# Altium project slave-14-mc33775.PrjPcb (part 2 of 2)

## Sheet dcdc-converter.SchDoc
size A3; DocumentNumber: 9; SheetNumber: 9; SheetTotal: 11; SheetDescription: DC/DC-Converter
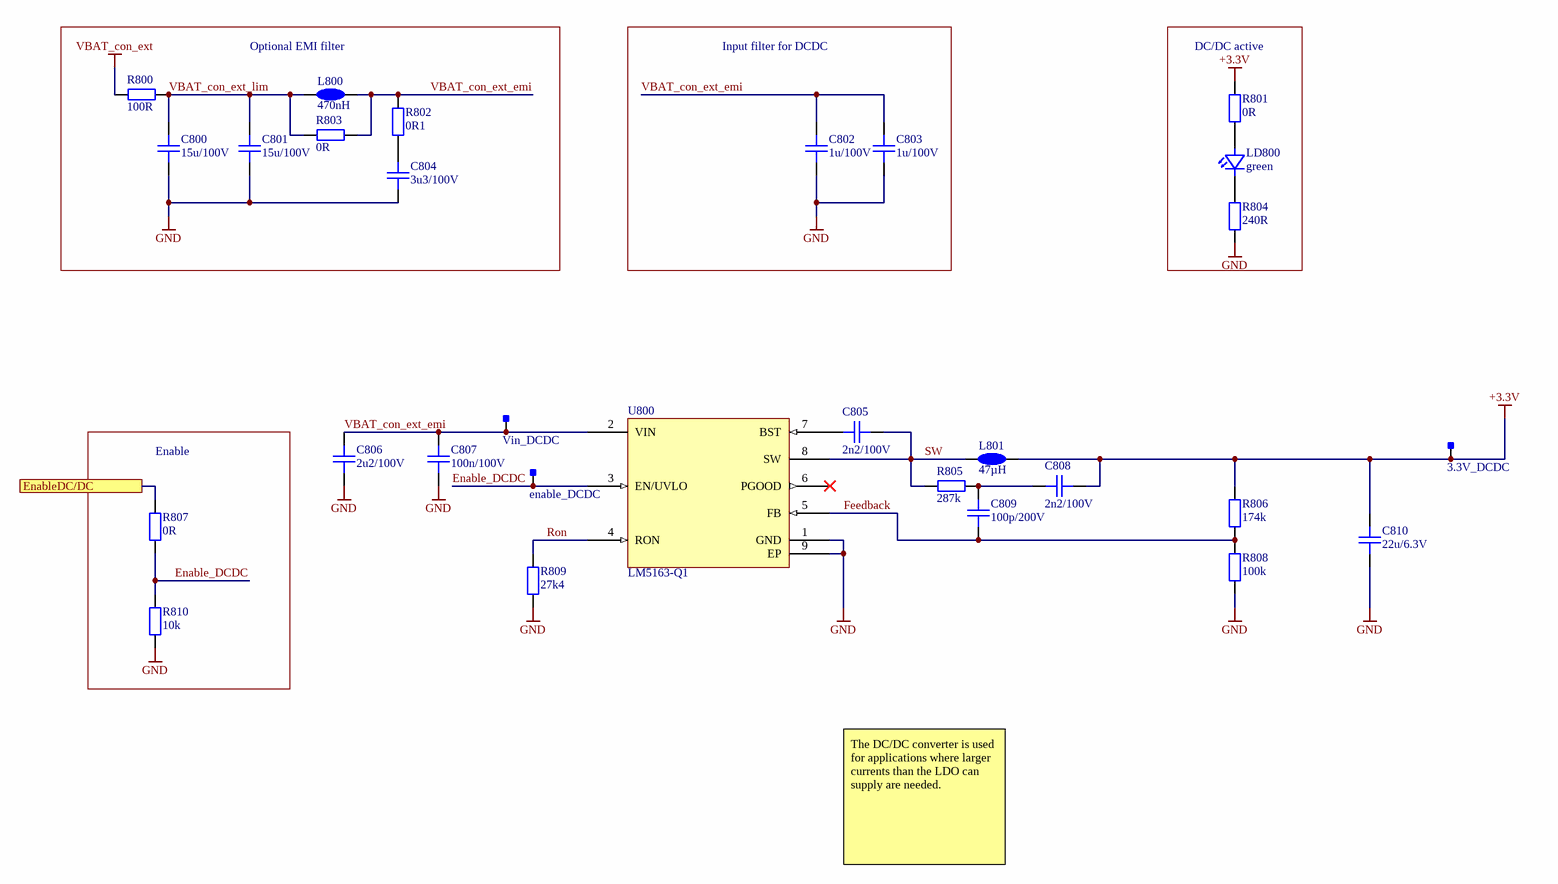
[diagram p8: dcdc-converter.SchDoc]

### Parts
3.3V_DCDC  Testpoint_Square  [Testpoint_S1]  (value not drawn)  (no BOM)
C800  15u/100V  [CAPC6153X67N]
C801  15u/100V  [CAPC6153X67N]
C802  1u/100V  [CAPC3225X25N]
C803  1u/100V  [CAPC3225X25N]
C804  3u3/100V  [CAPC4532X16N]
C805  2n2/100V  [CAPC1005X06N]
C806  2u2/100V  [CAPC3225X25N]
C807  100n/100V  [CAPC1608X08N]
C808  2n2/100V  [CAPC1005X06N]
C809  100p/200V  [CAPC1005X06N]
C810  22u/6.3V  [CAPC3216X18N]
enable_DCDC  Testpoint_Square  [Testpoint_S1]  (value not drawn)  (no BOM)
L800  470nH  [SRP7028A]
L801  47µH  [TYS6045470M-10]
LD800  green  [LEDC1608X07N]
R800  100R  [RESC1608X05N]
R801  0R  [RESC1608X05N]
R802  0R1  [RESC2012X05N]
R803  0R  [RESC1608X05N]
R804  240R  [RESC1608X05N]
R805  287k  [RESC1608X05N]
R806  174k  [RESC1608X05N]
R807  0R  [RESC1608X05N]
R808  100k  [RESC1608X05N]
R809  27k4  [RESC1608X05N]
R810  10k  [RESC1608X05N]
U800  LM5163-Q1  [R-PDSO-G8]
Vin_DCDC  Testpoint_Square  [Testpoint_S1]  (value not drawn)  (no BOM)

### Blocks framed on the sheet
Optional EMI filter: C800 C801 C804 L800 R800 R802 R803
Input filter for DCDC: C802 C803
DC/DC active: LD800 R801 R804
Enable: R807 R810

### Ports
EnableDC/DC

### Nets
+3.3V: 3.3V_DCDC.1 C808.2 C810.2 L801.2 R801.2 R806.2
GND: C800.1 C801.1 C802.1 C803.1 C804.1 C806.1 C807.1 C810.1 R804.1 R808.1 R809.1 R810.2 U800.1(GND) U800.9(EP)
VBAT_con_ext: R800.1
Enable_DCDC: enable_DCDC.1 R807.2 R810.1 U800.3(EN/UVLO)
Feedback: C809.1 R806.1 R808.2 U800.5(FB)
Ron: R809.2 U800.4(RON)
SW: C805.2 L801.1 R805.1 U800.8(SW)
VBAT_con_ext_emi: C802.2 C803.2 C806.2 C807.2 L800.2 R802.2 R803.2 U800.2(VIN) Vin_DCDC.1
VBAT_con_ext_lim: C800.2 C801.2 L800.1 R800.2 R803.1
NetC804_2: C804.2 R802.1
NetC805_1: C805.1 U800.7(BST)
NetC808_1: C808.1 C809.2 R805.2
NetLD800_1: LD800.1(C) R804.2
NetLD800_2: LD800.2(A) R801.1
NetR601_2: R807.1 ; port EnableDC/DC

Not connected (* = marked no-connect by the designer): U800 6(PGOOD)*

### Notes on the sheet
- The DC/DC converter is used for applications where larger currents than the LDO can supply are needed.

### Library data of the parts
3.3V_DCDC enable_DCDC Vin_DCDC = Testpoint_Square: Testpoint, square; Automotive Qualified: False
C800 C801 = gen_C_ceramic_15u_100V_X7R_2220: Stacked MLCC; Capacitance: 15u; Rated Voltage: 100V; Dielectric: X7R; Case EIA: 2220; Case Metric: 5750; Automotive Qualified: True
C802 C803 = gen_C_ceramic_1u_100V_X7R_1210: MLCC; Capacitance: 1u; Rated Voltage: 100V; Dielectric: X7R; Case EIA: 1210; Case Metric: 3225; AVT Set: x; Automotive Qualified: True
C804 = gen_C_ceramic_3u3_100V_X7R_1812: MLCC; Capacitance: 3u3; Rated Voltage: 100V; Dielectric: X7R; Case EIA: 1812; Case Metric: 4532; Automotive Qualified: True
C805 = gen_C_ceramic_2n2_100V_X7R_0402: MLCC; Capacitance: 2n2; Rated Voltage: 100V; Dielectric: X7R; Case EIA: 0402; Case Metric: 1005; Automotive Qualified: True; PnP Package: 0402C
C806 = gen_C_ceramic_2u2_100V_X7R_1210: MLCC; Capacitance: 2u2; Rated Voltage: 100V; Dielectric: X7R; Case EIA: 1210; Case Metric: 3225; AVT Set: x; Automotive Qualified: True
C807 = gen_C_ceramic_100n_100V_X7R_0603: MLCC; Capacitance: 100n; Rated Voltage: 100V; Dielectric: X7R; Case EIA: 0603; Case Metric: 1608; Automotive Qualified: True; PnP Package: 0603C
C808 = gen_C_ceramic_2n2_100V_X7R_0402: MLCC; Capacitance: 2n2; Rated Voltage: 100V; Dielectric: X7R; Case EIA: 0402; Case Metric: 1005; PnP Package: 0402C; Automotive Qualified: True
C809 = gen_C_ceramic_100p_200V_C0G_0402: MLCC; Capacitance: 100p; Rated Voltage: 200V; Dielectric: C0G; Tolerance: 5%; Case EIA: 0402; Case Metric: 1005; PnP Package: 0402C; Automotive Qualified: True
C810 = gen_C_ceramic_22u_6V3_X7R_1206: MLCC; Capacitance: 22u; Rated Voltage: 6.3V; Dielectric: X7R; Case EIA: 1206; Case Metric: 3216; Automotive Qualified: True
L800 = SRP7028A-R47M: FIXED IND 470NH 17.5A 4.2 MOHM; Manufacturer: Bourns Inc; Saturation Current: 26A; Automotive Qualified: True
L801 = TYS6045470M-10: Power Inductor; Manufacturer: Laird-Signal Integrity Products; Rated Current: 1.2A; Saturation Current: 1.4A; Automotive Qualified: True
LD800 = LED_0603_green_AECQ: TLMG1100-GS08; Manufacturer: Vishay; Breakdown Voltage: 5V; Continuous Forward Current: 20mA; Forward Voltage @ 20mA: 2.1V; Automotive Qualified: True
R800 = gen_R_100R_0603: SMD Resistor 100R 0603; Tolerance: 1%; Power: 0.1W; Case EIA: 0603; Case Metric: 1608; Maximum Working Voltage: 75V; PnP Package: 0603R; Automotive Qualified: True; PnP equipped: x
R801 R803 R807 = gen_R_0R_0603: SMD Resistor 0R 0603; Power: 0.1W; Case EIA: 0603; Case Metric: 1608; Maximum Working Voltage: 75V; PnP Package: 0603R; Automotive Qualified: True; PnP equipped: x
R802 = gen_R_0R1_0805: SMD Resistor 0R1 0805; Power: 250mW; Case EIA: 0805; Maximum Working Voltage: 150V; Automotive Qualified: True
R804 = gen_R_240R_0603: SMD Resistor 240R 0603; Tolerance: 1%; Power: 0.1W; Case EIA: 0603; Case Metric: 1608; Maximum Working Voltage: 75V; PnP Package: 0603R; Automotive Qualified: True; AEC-Q Norm: AEC-Q200
R805 = gen_R_287k_0603: SMD Resistor 287k 0603; Tolerance: 1%; Power: 0.1W; Case EIA: 0603; Case Metric: 1608; Maximum Working Voltage: 75V; PnP Package: 0603R; Automotive Qualified: True; AEC-Q Norm: AEC-Q200
R806 = gen_R_174k_0603: SMD Resistor 174k 0603; Tolerance: 1%; Power: 0.1W; Case EIA: 0603; Case Metric: 1608; Maximum Working Voltage: 75V; PnP Package: 0603R; Automotive Qualified: True; AEC-Q Norm: AEC-Q200
R808 = gen_R_100k_0603: SMD Resistor 100k 0603; Tolerance: 1%; Power: 0.1W; Case EIA: 0603; Case Metric: 1608; Maximum Working Voltage: 75V; PnP Package: 0603R; Automotive Qualified: True; PnP equipped: x
R809 = gen_R_27k4_0603: SMD Resistor 27k4 0603; Tolerance: 1%; Power: 0.1W; Case EIA: 0603; Case Metric: 1608; Maximum Working Voltage: 75V; PnP Package: 0603R; Automotive Qualified: True; AEC-Q Norm: AEC-Q 200
R810 = gen_R_10k_0603: SMD Resistor 10k 0603; Tolerance: 1%; Power: 0.1W; Case EIA: 0603; Case Metric: 1608; Maximum Working Voltage: 75V; PnP Package: 0603R; Automotive Qualified: True
U800 = LM5163-Q1: 100-V Input, 0.5-A SynchronousBuck DC/DCConverterwith Ultra-lowIQ; Manufacturer: Texas Instruments; Automotive Qualified: True

## Sheet sensors.SchDoc
size A3; DocumentNumber: 10; SheetNumber: 10; SheetTotal: 11; SheetDescription: Environmental Sensors
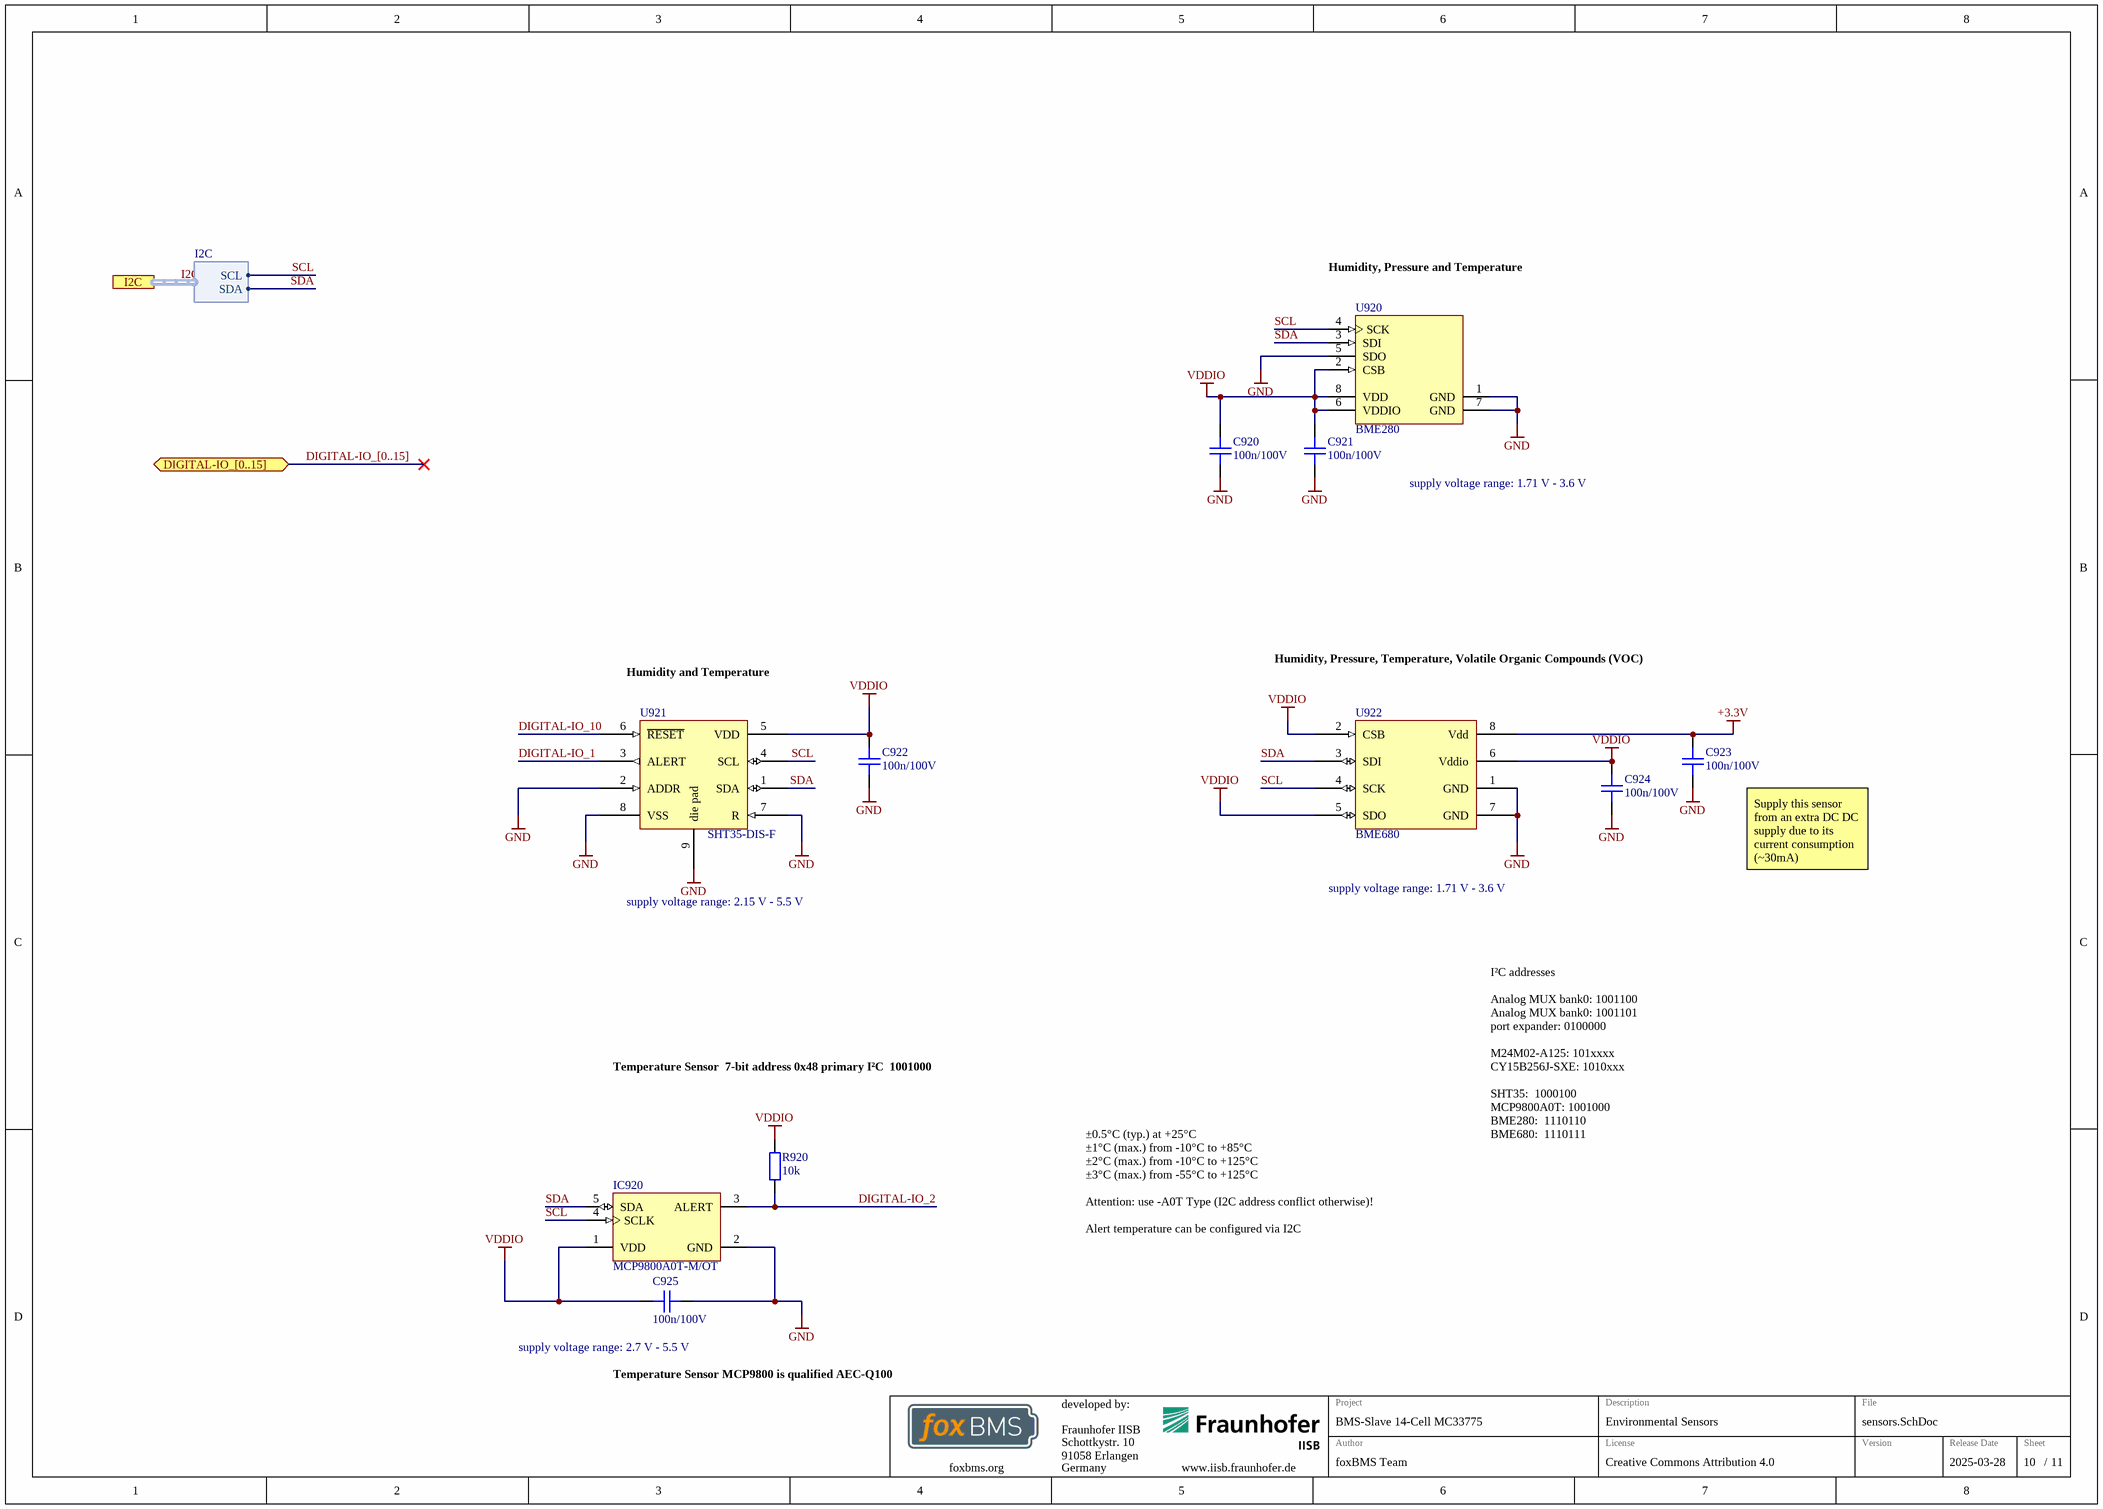
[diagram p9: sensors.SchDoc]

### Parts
C920  100n/100V  [CAPC1608X08N]
C921  100n/100V  [CAPC1608X08N]
C922  100n/100V  [CAPC1608X08N]
C923  100n/100V  [CAPC1608X08N]
C924  100n/100V  [CAPC1608X08N]
C925  100n/100V  [CAPC1608X08N]
IC920  MCP9800A0T-M/OT  [SOT-23-OT5_L]
R920  10k  [RESC1608X05N]
U920  BME280  [BOSC-BME280-8_V]
U921  SHT35-DIS-F  [SHT3X]
U922  BME680  [BME680]

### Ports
DIGITAL-IO_[0..15] (bidir), I2C (harness I2C)

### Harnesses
I2C: SCL, SDA

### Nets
+3.3V: C923.2 U922.8(Vdd)
GND: C920.1 C921.1 C922.1 C923.1 C924.1 C925.1 IC920.2(GND) U920.1(GND) U920.5(SDO) U920.7(GND) U921.2(ADDR) U921.7(R) U921.8(VSS) U921.9(die_pad) U922.1(GND) U922.7(GND)
VDDIO: C920.2 C921.2 C922.2 C924.2 C925.2 IC920.1(VDD) R920.2 U920.2(CSB) U920.6(VDDIO) U920.8(VDD) U921.5(VDD) U922.2(CSB) U922.5(SDO) U922.6(Vddio)
DIGITAL-IO_1: U921.3(ALERT)
DIGITAL-IO_2: IC920.3(ALERT) R920.1
DIGITAL-IO_10: U921.6(~{RESET})
SCL: IC920.4(SCLK) U920.4(SCK) U921.4(SCL) U922.4(SCK) ; port I2C.SCL  [project net I2C.SCL]
SDA: IC920.5(SDA) U920.3(SDI) U921.1(SDA) U922.3(SDI) ; port I2C.SDA  [project net I2C.SDA]

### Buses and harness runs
bus DIGITAL-IO_[0..15] = port DIGITAL-IO_[0..15]
harness I2C = port I2C

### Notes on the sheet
- Humidity, Pressure and Temperature
- supply voltage range: 1.71 V - 3.6 V
- Humidity and Temperature
- Humidity, Pressure, Temperature, Volatile Organic Compounds (VOC)
- supply voltage range: 2.15 V - 5.5 V
- Supply this sensor from an extra DC DC supply due to its current consumption (~30mA)
- Temperature Sensor
  7-bit address 0x48 primary I²C
  1001000
- ±0.5°C (typ.) at +25°C
  ±1°C (max.) from -10°C to +85°C
  ±2°C (max.) from -10°C to +125°C
  ±3°C (max.) from -55°C to +125°C
  Attention: use -A0T Type (I2C address conflict otherwise)!
  Alert temperature can be configured via I2C
- I²C addresses
  Analog MUX bank0:	1001100
  Analog MUX bank0:	1001101
  port expander:	0100000
  M24M02-A125:	101xxxx
  CY15B256J-SXE:	1010xxx
  SHT35:		1000100
  MCP9800A0T:	1001000
  BME280:		1110110
  BME680:		1110111
- (near C925) supply voltage range: 2.7 V - 5.5 V
- Temperature Sensor MCP9800 is qualified AEC-Q100

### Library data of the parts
C920-C925 = gen_C_ceramic_100n_100V_X7R_0603: as C807 on sheet dcdc-converter
IC920 = CMP-0192-00211-1: 2-Wire High-Accuracy Temperature Sensor, Slave Address 000, 5-Pin SOT-23, -55°C to +125°C Temperature, Tape and Reel
R920 = gen_R_10k_0603: as R810 on sheet dcdc-converter
U920 = BME280: Low power pressure, temperature & humidity sensor; Manufacturer: Bosch Sensortec; PnP Package: LGA; Automotive Qualified: False
U921 = SHT35-DIS-F: Humidity/Temp Sensor, Digital, Dfn-8; Manufacturer: Sensirion; PnP Package: DFN; Automotive Qualified: True
U922 = BME680: Low power gas, pressure, temperature & humidity sensor; Manufacturer: Bosch Sensortec; PnP Package: LGA; Automotive Qualified: False

## Sheet digital_io.SchDoc: foxBMS BMS-Slave 12-Cell
size A3; DocumentNumber: 11; SheetNumber: 11; SheetTotal: 11; AUTHOR: Fraunhofer IISB foxBMS Team; SheetDescription: Digital Inputs/Outputs
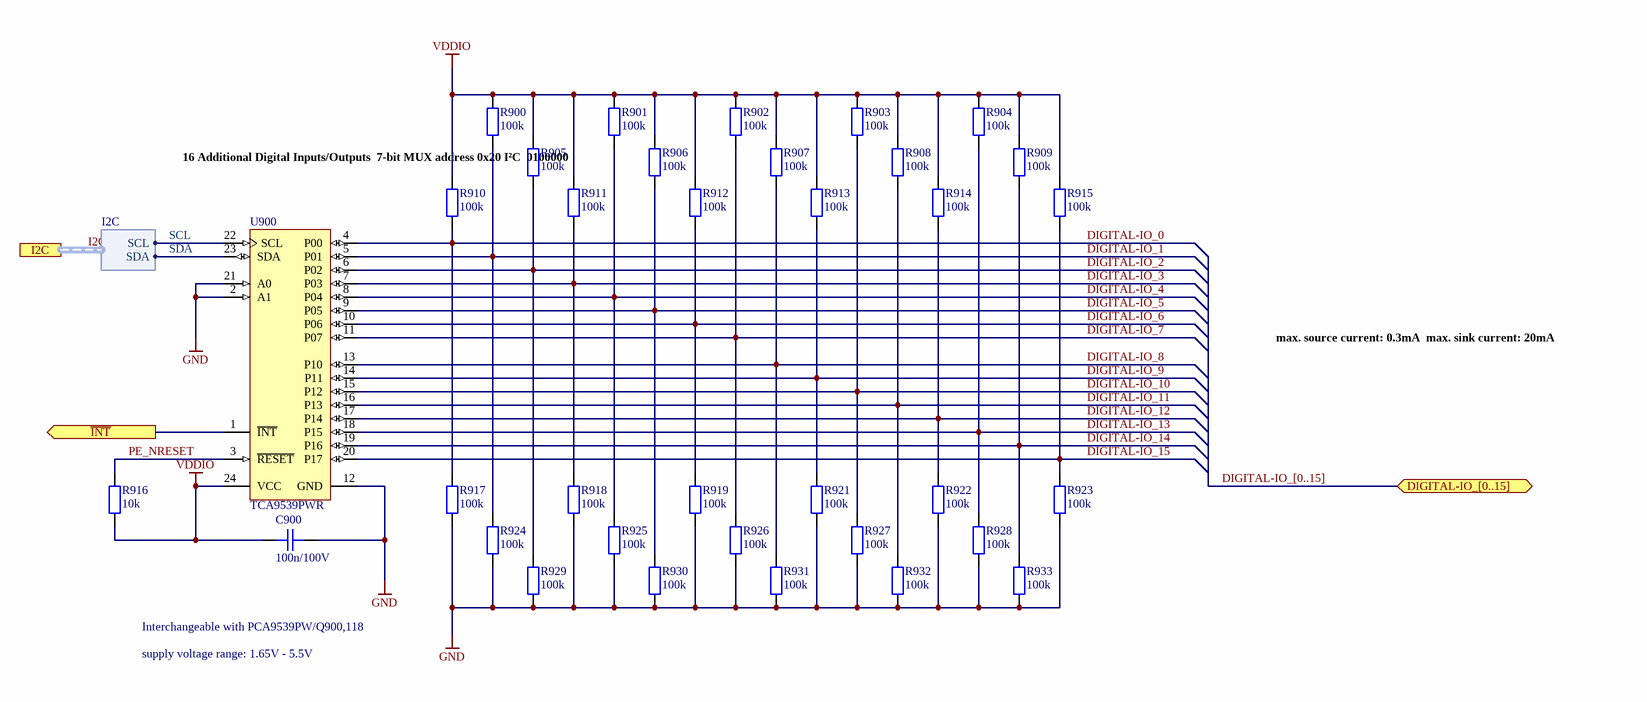
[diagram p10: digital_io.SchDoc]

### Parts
C900  100n/100V  [CAPC1608X08N]
R900  100k  [RESC1608X05N]
R901  100k  [RESC1608X05N]
R902  100k  [RESC1608X05N]
R903  100k  [RESC1608X05N]
R904  100k  [RESC1608X05N]
R905  100k  [RESC1608X05N]
R906  100k  [RESC1608X05N]
R907  100k  [RESC1608X05N]
R908  100k  [RESC1608X05N]
R909  100k  [RESC1608X05N]
R910  100k  [RESC1608X05N]
R911  100k  [RESC1608X05N]
R912  100k  [RESC1608X05N]
R913  100k  [RESC1608X05N]
R914  100k  [RESC1608X05N]
R915  100k  [RESC1608X05N]
R916  10k  [RESC1608X05N]
R917  100k  [RESC1608X05N]
R918  100k  [RESC1608X05N]
R919  100k  [RESC1608X05N]
R921  100k  [RESC1608X05N]
R922  100k  [RESC1608X05N]
R923  100k  [RESC1608X05N]
R924  100k  [RESC1608X05N]
R925  100k  [RESC1608X05N]
R926  100k  [RESC1608X05N]
R927  100k  [RESC1608X05N]
R928  100k  [RESC1608X05N]
R929  100k  [RESC1608X05N]
R930  100k  [RESC1608X05N]
R931  100k  [RESC1608X05N]
R932  100k  [RESC1608X05N]
R933  100k  [RESC1608X05N]
U900  TCA9539PWR  [PW0024A_M]

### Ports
DIGITAL-IO_[0..15] (bidir), I2C (harness I2C), ~{INT} (out)

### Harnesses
I2C: SCL, SDA

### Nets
GND: C900.1 R917.1 R918.1 R919.1 R921.1 R922.1 R923.1 R924.1 R925.1 R926.1 R927.1 R928.1 R929.1 R930.1 R931.1 R932.1 R933.1 U900.2(A1) U900.12(GND) U900.21(A0)
VDDIO: C900.2 R900.2 R901.2 R902.2 R903.2 R904.2 R905.2 R906.2 R907.2 R908.2 R909.2 R910.2 R911.2 R912.2 R913.2 R914.2 R915.2 R916.1 U900.24(VCC)
DIGITAL-IO_0: R910.1 R917.2 U900.4(P00)
DIGITAL-IO_1: R900.1 R924.2 U900.5(P01)
DIGITAL-IO_2: R905.1 R929.2 U900.6(P02)
DIGITAL-IO_3: R911.1 R918.2 U900.7(P03)
DIGITAL-IO_4: R901.1 R925.2 U900.8(P04)
DIGITAL-IO_5: R906.1 R930.2 U900.9(P05)
DIGITAL-IO_6: R912.1 R919.2 U900.10(P06)
DIGITAL-IO_7: R902.1 R926.2 U900.11(P07)
DIGITAL-IO_8: R907.1 R931.2 U900.13(P10)
DIGITAL-IO_9: R913.1 R921.2 U900.14(P11)
DIGITAL-IO_10: R903.1 R927.2 U900.15(P12)
DIGITAL-IO_11: R908.1 R932.2 U900.16(P13)
DIGITAL-IO_12: R914.1 R922.2 U900.17(P14)
DIGITAL-IO_13: R904.1 R928.2 U900.18(P15)
DIGITAL-IO_14: R909.1 R933.2 U900.19(P16)
DIGITAL-IO_15: R915.1 R923.2 U900.20(P17)
INT: U900.1(~{INT}) ; port ~{INT}
PE_NRESET: R916.2 U900.3(~{RESET})
SCL: U900.22(SCL) ; port I2C.SCL  [project net I2C.SCL]
SDA: U900.23(SDA) ; port I2C.SDA  [project net I2C.SDA]

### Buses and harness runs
bus DIGITAL-IO_[0..15] = port DIGITAL-IO_[0..15]
harness I2C = port I2C

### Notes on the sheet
- (near R905) 16 Additional Digital Inputs/Outputs
  7-bit MUX address 0x20 I²C
  0100000
- max. source current: 0.3mA
  max. sink current: 20mA
- Interchangeable with PCA9539PW/Q900,118
- supply voltage range: 1.65V - 5.5V

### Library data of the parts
C900 = gen_C_ceramic_100n_100V_X7R_0603: as C807 on sheet dcdc-converter
R900-R915 R917-R919 R921-R933 = gen_R_100k_0603: as R808 on sheet dcdc-converter
R916 = gen_R_10k_0603: as R810 on sheet dcdc-converter
U900 = CMP-0314-00251-2: Remote 16-Bit I2C and SMBus, Low-Power I/O Expander with Interrupt Output, Reset & Config. Register, 1.65 to 5.5 V, -40 to 85 degC, 24-pin TSSOP (PW), Green (RoHS & no Sb/Br); Manufacturer: Texas Instruments; Interrupt Output: Yes; SubFamily: I2C IO Expander; I2C Address: 1110 1xx; # of I/Os: 16; Max Frequency(kHz): 400

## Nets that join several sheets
+3.3V: connectors (J308.10 J309.10), dcdc-converter (6 pins), sensors (C923.2 U922.8)
GND: mc33775 (38 pins), ldo (8 pins), eeprom (C400.1 U400.1 U400.2 U400.4), input_filter (32 pins), passive_balancing (14 pins), U_analog_in_bank0 (27 pins), connectors (26 pins), dcdc-converter (14 pins), sensors (16 pins), digital_io (20 pins), U_analog_in_bank1 (27 pins)
VAUX: mc33775 (7 pins), passive_balancing (R700.2 R701.2), U_analog_in_bank0 (R200_1.2), connectors (J308.12 J309.12), U_analog_in_bank1 (R200_2.2)
VBAT_con: mc33775 (D600.2), connectors (J300.9)
VBAT_con_ext: mc33775 (9 pins), connectors (J311.1 J312.1), dcdc-converter (R800.1)
VBAT_ext: mc33775 (D601.2), connectors (J310.1)
VDDC: mc33775 (12 pins), ldo (C850.2 R851.2 U850.8 U851.8), U_analog_in_bank0 (C200_1.2 C201_1.2 U200_1.2), connectors (J308.11 J309.11), U_analog_in_bank1 (C200_2.2 C201_2.2 U200_2.2)
VDDIO: mc33775 (R616.2 R617.2 R637.1 U600.39), ldo (3.3V_LDO.1 R850.2), eeprom (C400.2 R400.2 R401.2 U400.8), U_analog_in_bank0 (7 pins), connectors (J308.9 J309.9), sensors (14 pins), digital_io (19 pins), U_analog_in_bank1 (7 pins)
VMODULE: mc33775 (U600.17 Vmodule.1), input_filter (C531.2 R515.1)
AL_IN._N: mc33775 (C616.2 D610.3 U601.12), connectors (J305.2)
AL_IN._P: mc33775 (C616.1 D610.1 D610.2 U601.11), connectors (J305.1)
AL_OUT._N: mc33775 (C614.1 R632.2), connectors (J306.2)
AL_OUT._P: mc33775 (C614.2 R628.2), connectors (J306.1)
ALARM_IN: mc33775 (ALARM_IN.1 Q602.D R607.1 R641.2), connectors (J308.7 J309.7)
ALARM_OUT: mc33775 (ALARM_OUT.1 R627.2 R634.1 U600.57), connectors (J308.8 J309.8)
BAL.CB_COM1: mc33775 (U600.37), input_filter (C522.2 R511.2), connectors (J300.2)
BAL.CB_COM3: mc33775 (U600.34), input_filter (C514.2 R507.2), connectors (J300.3)
BAL.CB_COM5: mc33775 (U600.31), input_filter (C506.2 R503.2 R517.1), connectors (J300.4)
BAL.CB_COM7: mc33775 (U600.28), input_filter (C528.2 R514.2 R519.1), connectors (J300.5)
BAL.CB_COM9: mc33775 (U600.25), input_filter (C520.2 R510.2 R521.1), connectors (J300.6)
BAL.CB_COM11: mc33775 (U600.22), input_filter (C512.2 R506.2 R523.1), connectors (J300.7)
BAL.CB_COM13: mc33775 (D603.2 U600.19), input_filter (C504.2 R502.2 R525.1), connectors (J300.8)
BAL.CB_HI2: mc33775 (U600.36), passive_balancing (R715.2 R729.2)
BAL.CB_HI4: mc33775 (U600.33), passive_balancing (R717.2 R731.2)
BAL.CB_HI6: mc33775 (U600.30), passive_balancing (R719.2 R733.2)
BAL.CB_HI8: mc33775 (U600.27), passive_balancing (R721.2 R735.2)
BAL.CB_HI10: mc33775 (U600.24), passive_balancing (R723.2 R737.2)
BAL.CB_HI12: mc33775 (U600.21), passive_balancing (R725.2 R739.2)
BAL.CB_HI14: mc33775 (U600.18), passive_balancing (R727.1 R741.1)
BAL.CB_LO0: mc33775 (U600.38), passive_balancing (R714.1 R728.1)
BAL.CB_LO2: mc33775 (U600.35), passive_balancing (R716.1 R730.1)
BAL.CB_LO4: mc33775 (U600.32), passive_balancing (R718.1 R732.1)
BAL.CB_LO6: mc33775 (U600.29), passive_balancing (R720.1 R734.1)
BAL.CB_LO8: mc33775 (U600.26), passive_balancing (R722.1 R736.1)
BAL.CB_LO10: mc33775 (U600.23), passive_balancing (R724.1 R738.1)
BAL.CB_LO12: mc33775 (U600.20), passive_balancing (R726.1 R740.1)
BAL_NTC0: mc33775 (R613.1), passive_balancing (C701.2 R702.1)
BAL_NTC1: mc33775 (R614.1), passive_balancing (C703.2 R703.1)
CIN0: input_filter (C526.2 R513.2), passive_balancing (R706.1 R714.2 R728.2), connectors (J300.13)
CIN2: input_filter (C518.2 R509.2), passive_balancing (5 pins), connectors (J300.14)
CIN4: input_filter (C510.2 R505.2 R516.1), passive_balancing (5 pins), connectors (J300.15)
CIN6: input_filter (C502.2 R501.2 R518.1), passive_balancing (5 pins), connectors (J300.16)
CIN8: input_filter (C524.2 R512.2 R520.1), passive_balancing (5 pins), connectors (J300.17)
CIN10: input_filter (C516.2 R508.2 R522.1), passive_balancing (5 pins), connectors (J300.18)
CIN12: input_filter (C508.2 R504.2 R524.1), passive_balancing (5 pins), connectors (J300.19)
CIN14: input_filter (C500.2 R500.2 R526.1), passive_balancing (R713.1 R727.2 R741.2), connectors (J300.20)
CT0: mc33775 (U600.16), input_filter (C527.2 R513.1)
CT1: mc33775 (U600.15), input_filter (C523.2 R511.1)
CT2: mc33775 (U600.14), input_filter (C519.2 R509.1)
CT3: mc33775 (U600.13), input_filter (C515.2 R507.1)
CT4: mc33775 (U600.12), input_filter (C511.2 R505.1)
CT5: mc33775 (U600.11), input_filter (C507.2 R503.1)
CT6: mc33775 (U600.10), input_filter (C503.2 R501.1)
CT7: mc33775 (U600.9), input_filter (C529.2 R514.1)
CT8: mc33775 (U600.8), input_filter (C525.2 R512.1)
CT9: mc33775 (U600.7), input_filter (C521.2 R510.1)
CT10: mc33775 (U600.6), input_filter (C517.2 R508.1)
CT11: mc33775 (U600.5), input_filter (C513.2 R506.1)
CT12: mc33775 (U600.4), input_filter (C509.2 R504.1)
CT13: mc33775 (U600.3), input_filter (C505.2 R502.1)
CT14: mc33775 (U600.2), input_filter (C501.2 R500.1)
DIGITAL-IO_0: connectors (J303.1), digital_io (R910.1 R917.2 U900.4)
DIGITAL-IO_1: connectors (J303.2), sensors (U921.3), digital_io (R900.1 R924.2 U900.5)
DIGITAL-IO_2: connectors (J303.3), sensors (IC920.3 R920.1), digital_io (R905.1 R929.2 U900.6)
DIGITAL-IO_3: connectors (J303.4), digital_io (R911.1 R918.2 U900.7)
DIGITAL-IO_4: connectors (J303.5), digital_io (R901.1 R925.2 U900.8)
DIGITAL-IO_5: connectors (J303.6), digital_io (R906.1 R930.2 U900.9)
DIGITAL-IO_6: connectors (J303.7), digital_io (R912.1 R919.2 U900.10)
DIGITAL-IO_7: connectors (J303.8), digital_io (R902.1 R926.2 U900.11)
DIGITAL-IO_8: connectors (J303.9), digital_io (R907.1 R931.2 U900.13)
DIGITAL-IO_9: connectors (J303.10), digital_io (R913.1 R921.2 U900.14)
DIGITAL-IO_10: connectors (J303.11), sensors (U921.6), digital_io (R903.1 R927.2 U900.15)
DIGITAL-IO_11: connectors (J303.12), digital_io (R908.1 R932.2 U900.16)
DIGITAL-IO_12: connectors (J303.13), digital_io (R914.1 R922.2 U900.17)
DIGITAL-IO_13: connectors (J303.14), digital_io (R904.1 R928.2 U900.18)
DIGITAL-IO_14: connectors (J303.15), digital_io (R909.1 R933.2 U900.19)
DIGITAL-IO_15: connectors (J303.16), digital_io (R915.1 R923.2 U900.20)
GPIO2_ext: mc33775 (R623.1), connectors (J308.1 J309.1)
GPIO3_ext: mc33775 (R624.1), connectors (J308.2 J309.2)
GPIO6_ext: mc33775 (R625.1), connectors (J308.3 J309.3)
GPIO7_ext: mc33775 (R626.1), connectors (J308.4 J309.4)
I2C.SCL: mc33775 (R615.1 R616.1), eeprom (U400.6), U_analog_in_bank0 (U201_1.1), connectors (J308.5 J309.5), sensors (IC920.4 U920.4 U921.4 U922.4), digital_io (U900.22), U_analog_in_bank1 (U201_2.1)
I2C.SDA: mc33775 (R617.1 R620.1), eeprom (U400.5), U_analog_in_bank0 (U201_1.3), connectors (J308.6 J309.6), sensors (IC920.5 U920.3 U921.1 U922.3), digital_io (U900.23), U_analog_in_bank1 (U201_2.3)
INT: mc33775 (R609.1), digital_io (U900.1)
MUX-DATA_IN: slave-14-mc33775 (R100.1), U_analog_in_bank0 (R230_1.2)
MUX_DATA: mc33775 (R606.1), U_analog_in_bank0 (C221_1.2 R231_1.2)
MUX_DATA2: slave-14-mc33775 (R100.2), mc33775 (R608.1), U_analog_in_bank1 (C221_2.2 R231_2.2)
NetR601_2: mc33775 (R601.2), dcdc-converter (R807.1)
T-SENSOR_0: U_analog_in_bank0 (C204_1.2 R221_1.1 R222_1.2), connectors (J304.1)
T-SENSOR_0: connectors (J307.1), U_analog_in_bank1 (C204_2.2 R221_2.1 R222_2.2)
T-SENSOR_1: U_analog_in_bank0 (C205_1.2 R209_1.1 R223_1.2), connectors (J304.2)
T-SENSOR_1: connectors (J307.2), U_analog_in_bank1 (C205_2.2 R209_2.1 R223_2.2)
T-SENSOR_2: U_analog_in_bank0 (C206_1.2 R220_1.1 R224_1.2), connectors (J304.3)
T-SENSOR_3: U_analog_in_bank0 (C207_1.2 R208_1.1 R225_1.2), connectors (J304.4)
T-SENSOR_4: U_analog_in_bank0 (C208_1.2 R219_1.1 R226_1.2), connectors (J304.5)
T-SENSOR_5: U_analog_in_bank0 (C209_1.2 R207_1.1 R227_1.2), connectors (J304.6)
T-SENSOR_6: U_analog_in_bank0 (C210_1.2 R218_1.1 R228_1.2), connectors (J304.7)
T-SENSOR_7: U_analog_in_bank0 (C211_1.2 R206_1.1 R229_1.2), connectors (J304.8)
T-SENSOR_10: connectors (J307.3), U_analog_in_bank1 (C206_2.2 R220_2.1 R224_2.2)
T-SENSOR_11: connectors (J307.4), U_analog_in_bank1 (C207_2.2 R208_2.1 R225_2.2)
T-SENSOR_12: connectors (J307.5), U_analog_in_bank1 (C208_2.2 R219_2.1 R226_2.2)
T-SENSOR_13: connectors (J307.6), U_analog_in_bank1 (C209_2.2 R207_2.1 R227_2.2)
T-SENSOR_14: connectors (J307.7), U_analog_in_bank1 (C210_2.2 R218_2.1 R228_2.2)
T-SENSOR_15: connectors (J307.8), U_analog_in_bank1 (C211_2.2 R206_2.1 R229_2.2)
T_FILT0: mc33775 (R629.1), U_analog_in_bank0 (R210_1.2)
T_FILT1: mc33775 (R630.1), U_analog_in_bank0 (R211_1.2)
T_FILT2: mc33775 (R631.1), U_analog_in_bank0 (R212_1.2)
T_FILT3: mc33775 (R633.1), U_analog_in_bank0 (R213_1.2)
T_FILT4: mc33775 (R635.1), U_analog_in_bank0 (R214_1.2)
T_FILT5: mc33775 (R636.1), U_analog_in_bank0 (R215_1.2)
T_FILT6: mc33775 (R639.1), U_analog_in_bank0 (R216_1.2)
T_FILT7: mc33775 (R640.1), U_analog_in_bank0 (R217_1.2)
TPL_H._N: mc33775 (R612.2), connectors (J301.2)
TPL_H._P: mc33775 (R610.2), connectors (J301.1)
TPL_L._N: mc33775 (R622.2), connectors (J302.2)
TPL_L._P: mc33775 (R619.2), connectors (J302.1)

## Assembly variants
foxBMS_14cell_BMS-Slave_NXP775A_minimal: not fitted ALARM_IN C200_1 C201_1 C203_1 C220_1 C221_1 C400 C614 C615 C616 C617 C618 C800 C801 C802 C803 C804 C805 C806 C807 C808 C809 C810 C850 C851 C852 C900 C920 C921 C922 C923 C924 C925 D601 D608 D609 D610 IC920 J303 J305 J306 J307 J308 J309 J310 J311 J312 L800 L801 LD800 LD850 Q601 Q602 R100 R201_1 R202_1 R203_1 R204_1 R205_1 R230_1 R231_1 R232_1 R400 R401 R516 R517 R518 R519 R520 R521 R522 R523 R524 R525 R601 R603 R606 R607 R608 R609 R613 R614 R615 R616 R617 R620 R623 R624 R625 R626 R628 R632 R634 R638 R641 R642 R643 R706 R707 R708 R709 R710 R711 R712 R713 R800 R801 R802 R803 R804 R805 R806 R807 R808 R809 R810 R850 R851 R852 R853 R854 R900 R901 R902 R903 R904 R905 R906 R907 R908 R909 R910 R911 R912 R913 R914 R915 R916 R917 R918 R919 R920 R921 R922 R923 R924 R925 R926 R927 R928 R929 R930 R931 R932 R933 U200_1 U201_1 U202_1 U400 U601 U800 U850 U851 U900 U920 U921 U922
foxBMS_14cell_BMS-Slave_NXP775A: not fitted C800 C801 C802 C803 C804 C805 C806 C807 C808 C809 C810 C920 C921 C923 C924 C925 IC920 J303 J305 J306 J308 J309 J310 J311 J312 L800 L801 LD800 R100 R200_2 R201_1 R202_1 R202_2 R203_1 R204_2 R210_1 R210_2 R211_1 R211_2 R212_1 R212_2 R213_1 R213_2 R214_1 R214_2 R215_1 R215_2 R216_1 R216_2 R217_1 R217_2 R230_1 R230_2 R516 R517 R518 R519 R520 R521 R522 R523 R524 R525 R603 R623 R624 R625 R626 R629 R630 R631 R633 R635 R636 R639 R640 R800 R801 R802 R803 R804 R805 R806 R807 R808 R809 R810 R850 R851 R853 R900 R901 R902 R904 R905 R906 R907 R908 R909 R910 R911 R912 R913 R914 R915 R917 R918 R919 R920 R921 R922 R923 R924 R925 R926 R927 R928 R929 R930 R931 R932 R933 U202_1 U202_2 U800 U850 U920 U922
foxBMS_14cell_BMS-Slave_Corvus: not fitted ALARM_IN C400 C614 C615 C616 C617 C618 C700 C701 C702 C703 C800 C801 C802 C803 C804 C805 C806 C807 C808 C809 C810 C850 C851 C852 C900 C920 C921 C922 C923 C924 C925 D601 D608 D609 D610 IC920 J303 J305 J306 J308 J309 J310 J311 J312 L800 L801 LD800 LD850 Q601 Q602 R100 R200_1 R200_2 R201_1 R202_1 R202_2 R204_2 R210_1 R210_2 R211_1 R211_2 R212_1 R212_2 R213_1 R213_2 R214_1 R214_2 R215_1 R215_2 R216_1 R216_2 R217_1 R217_2 R230_1 R230_2 R400 R401 R516 R517 R518 R519 R520 R521 R522 R523 R524 R525 R601 R603 R607 R609 R613 R614 R623 R624 R625 R626 R628 R629 R630 R631 R632 R633 R634 R635 R636 R638 R639 R640 R641 R642 R643 R700 R701 R702 R703 R704 R705 R706 R707 R708 R709 R710 R711 R712 R713 R800 R801 R802 R803 R804 R805 R806 R807 R808 R809 R810 R850 R851 R852 R853 R854 R900 R901 R902 R903 R904 R905 R906 R907 R908 R909 R910 R911 R912 R913 R914 R915 R916 R917 R918 R919 R920 R921 R922 R923 R924 R925 R926 R927 R928 R929 R930 R931 R932 R933 U202_1 U202_2 U400 U601 U800 U850 U851 U900 U920 U921 U922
